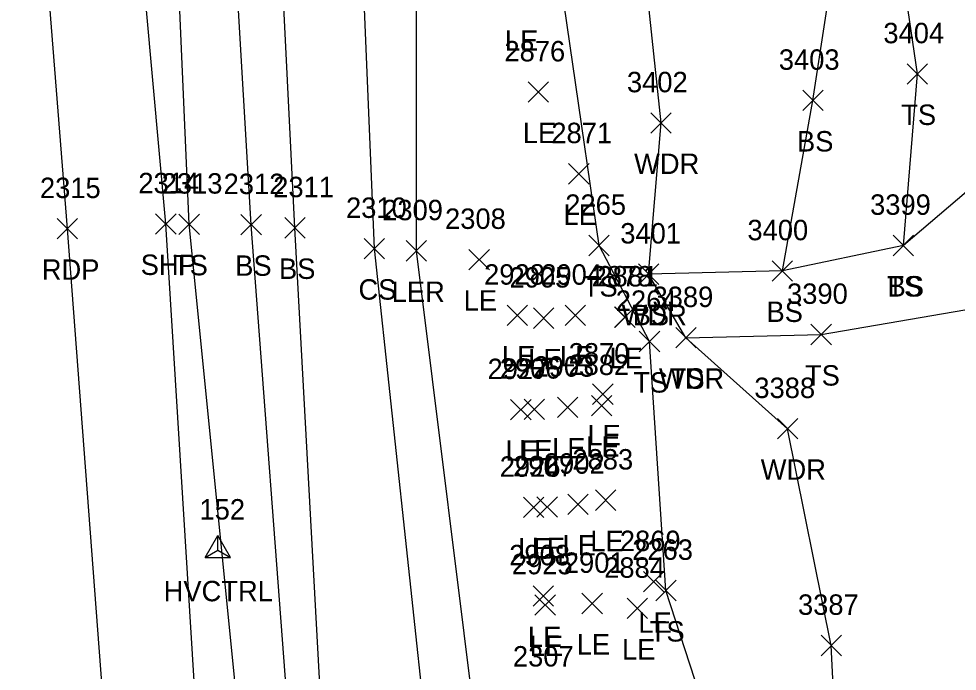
# Model space of a CAD drawing. Extents: x 1650221 to 1650634, y 244606 to 249996.
# Drawn here: x 1650346.1 to 1650438, y 246557.6 to 246621.5 of the extents above; entities that cross this region are included whole.
import ezdxf

# ---------------------------------------------------------------- set-up
doc = ezdxf.new("R2010")
doc.units = 0
for name, color, linetype in [('C_A', 7, 'Continuous'), ('C_I', 7, 'Continuous'), ('CPSM', 7, 'Continuous'), ('L_A', 7, 'Continuous'), ('L_I', 7, 'Continuous'), ('L_TIC', 7, 'Continuous'), ('LARO', 7, 'Continuous'), ('LAWA', 7, 'Continuous'), ('LELB', 7, 'Continuous'), ('P_A', 7, 'Continuous'), ('P_I', 7, 'Continuous'), ('P_TIC', 7, 'Continuous'), ('PET', 7, 'Continuous'), ('PSP', 7, 'Continuous')]:
    doc.layers.add(name, color=color, linetype=linetype)

msp = doc.modelspace()

# ---------------------------------------------------------------- linework, layer by layer
at = {"layer": 'CPSM'}
for p, q in [((1650364.338, 246568.725), (1650365.588, 246570.89)), ((1650366.838, 246568.725), (1650365.588, 246570.89)), ((1650365.588, 246569.447), (1650365.588, 246570.89)), ((1650364.338, 246568.725), (1650365.588, 246569.447)), ((1650365.588, 246569.447), (1650365.588, 246569.447)), ((1650365.588, 246569.447), (1650366.838, 246568.725)), ((1650364.338, 246568.725), (1650366.838, 246568.725))]:
    msp.add_line(p, q, dxfattribs=at)
at = {"layer": 'L_TIC'}
for points in [[(1650433.105, 246615.068), (1650435.105, 246617.068)], [(1650435.105, 246615.068), (1650433.105, 246617.068)], [(1650395.972, 246613.294), (1650397.972, 246615.294)], [(1650397.972, 246613.294), (1650395.972, 246615.294)], [(1650422.867, 246612.471), (1650424.867, 246614.471)], [(1650424.867, 246612.471), (1650422.867, 246614.471)], [(1650407.993, 246610.27), (1650409.993, 246612.27)], [(1650409.993, 246610.27), (1650407.993, 246612.27)], [(1650399.945, 246605.288), (1650401.945, 246607.288)], [(1650401.945, 246605.288), (1650399.945, 246607.288)], [(1650361.786, 246600.351), (1650363.786, 246602.351)], [(1650363.786, 246600.351), (1650361.786, 246602.351)], [(1650367.85, 246600.305), (1650369.85, 246602.305)], [(1650369.85, 246600.305), (1650367.85, 246602.305)], [(1650372.138, 246600), (1650374.138, 246602)], [(1650374.138, 246600), (1650372.138, 246602)], [(1650401.921, 246598.271), (1650403.921, 246600.271)], [(1650403.921, 246598.271), (1650401.921, 246600.271)], [(1650431.734, 246598.274), (1650433.734, 246600.274)], [(1650433.734, 246598.274), (1650431.734, 246600.274)], [(1650431.734, 246598.274), (1650433.734, 246600.274)], [(1650433.734, 246598.274), (1650431.734, 246600.274)], [(1650379.924, 246597.971), (1650381.924, 246599.971)], [(1650381.924, 246597.971), (1650379.924, 246599.971)], [(1650384.03, 246597.745), (1650386.03, 246599.745)], [(1650386.03, 246597.745), (1650384.03, 246599.745)], [(1650390.18, 246596.895), (1650392.18, 246598.895)], [(1650392.18, 246596.895), (1650390.18, 246598.895)], [(1650406.773, 246595.466), (1650408.773, 246597.466)], [(1650408.773, 246595.466), (1650406.773, 246597.466)], [(1650406.773, 246595.466), (1650408.773, 246597.466)], [(1650408.773, 246595.466), (1650406.773, 246597.466)], [(1650419.879, 246595.785), (1650421.879, 246597.785)], [(1650421.879, 246595.785), (1650419.879, 246597.785)], [(1650419.879, 246595.785), (1650421.879, 246597.785)], [(1650421.879, 246595.785), (1650419.879, 246597.785)], [(1650393.923, 246591.438), (1650395.923, 246593.438)], [(1650395.923, 246591.438), (1650393.923, 246593.438)], [(1650396.492, 246591.155), (1650398.492, 246593.155)], [(1650398.492, 246591.155), (1650396.492, 246593.155)], [(1650399.598, 246591.434), (1650401.598, 246593.434)], [(1650401.598, 246591.434), (1650399.598, 246593.434)], [(1650404.451, 246591.26), (1650406.451, 246593.26)], [(1650406.451, 246591.26), (1650404.451, 246593.26)], [(1650404.456, 246591.259), (1650406.456, 246593.259)], [(1650406.456, 246591.259), (1650404.456, 246593.259)], [(1650410.429, 246589.247), (1650412.429, 246591.247)], [(1650412.429, 246589.247), (1650410.429, 246591.247)], [(1650410.429, 246589.247), (1650412.429, 246591.247)], [(1650412.429, 246589.247), (1650410.429, 246591.247)], [(1650423.679, 246589.557), (1650425.679, 246591.557)], [(1650425.679, 246589.557), (1650423.679, 246591.557)], [(1650406.868, 246588.874), (1650408.868, 246590.874)], [(1650408.868, 246588.874), (1650406.868, 246590.874)], [(1650402.293, 246583.717), (1650404.293, 246585.717)], [(1650404.293, 246583.717), (1650402.293, 246585.717)], [(1650402.182, 246582.594), (1650404.182, 246584.594)], [(1650404.182, 246582.594), (1650402.182, 246584.594)], [(1650394.263, 246582.194), (1650396.263, 246584.194)], [(1650396.263, 246582.194), (1650394.263, 246584.194)], [(1650395.594, 246582.241), (1650397.594, 246584.241)], [(1650397.594, 246582.241), (1650395.594, 246584.241)], [(1650398.841, 246582.43), (1650400.841, 246584.43)], [(1650400.841, 246582.43), (1650398.841, 246584.43)], [(1650420.393, 246580.34), (1650422.393, 246582.34)], [(1650422.393, 246580.34), (1650420.393, 246582.34)], [(1650395.513, 246572.633), (1650397.513, 246574.633)], [(1650397.513, 246572.633), (1650395.513, 246574.633)], [(1650396.841, 246572.665), (1650398.841, 246574.665)], [(1650398.841, 246572.665), (1650396.841, 246574.665)], [(1650399.861, 246572.934), (1650401.861, 246574.934)], [(1650401.861, 246572.934), (1650399.861, 246574.934)], [(1650402.575, 246573.342), (1650404.575, 246575.342)], [(1650404.575, 246573.342), (1650402.575, 246575.342)], [(1650407.276, 246565.358), (1650409.276, 246567.358)], [(1650409.276, 246565.358), (1650407.276, 246567.358)], [(1650408.477, 246564.503), (1650410.477, 246566.503)], [(1650410.477, 246564.503), (1650408.477, 246566.503)], [(1650396.464, 246563.967), (1650398.464, 246565.967)], [(1650398.464, 246563.967), (1650396.464, 246565.967)], [(1650396.643, 246563.088), (1650398.643, 246565.088)], [(1650398.643, 246563.088), (1650396.643, 246565.088)], [(1650401.248, 246563.228), (1650403.248, 246565.228)], [(1650403.248, 246563.228), (1650401.248, 246565.228)], [(1650405.684, 246562.747), (1650407.684, 246564.747)], [(1650407.684, 246562.747), (1650405.684, 246564.747)], [(1650424.665, 246559.118), (1650426.665, 246561.118)], [(1650426.665, 246559.118), (1650424.665, 246561.118)]]:
    msp.add_lwpolyline(points, dxfattribs=at)
at = {"layer": 'LARO'}
msp.add_lwpolyline([(1650408.62, 246217.57), (1650415.017, 246258.551), (1650416.029, 246285.891), (1650409.424, 246296.822), (1650403.385, 246341.569), (1650407.268, 246374.549), (1650399.81, 246378.857), (1650397.578, 246413.378), (1650396.61, 246418.121), (1650404.549, 246441.775), (1650400.932, 246459.086), (1650402.014, 246482.667), (1650393.668, 246489.39), (1650391.868, 246506.076), (1650398.297, 246543.788), (1650391.282, 246548.764), (1650385.03, 246598.745), (1650385.051, 246648.918)], dxfattribs=at)
at = {"layer": 'LAWA'}
msp.add_lwpolyline([(1650467.45, 246241.248), (1650457.439, 246253.738), (1650465.182, 246273.586), (1650462.121, 246310.217), (1650448.311, 246306.896), (1650448.47, 246334.537), (1650451.184, 246360.806), (1650449.397, 246391.825), (1650443.671, 246414.288), (1650436.755, 246442.34), (1650433.959, 246470.022), (1650430.335, 246504.777), (1650427.125, 246530.837), (1650425.665, 246560.118), (1650421.393, 246581.34), (1650411.429, 246590.247), (1650407.773, 246596.466), (1650408.993, 246611.27), (1650406.472, 246635.271)], dxfattribs=at)
at = {"layer": 'LELB'}
for points in [[(1650393.271, 246215.062), (1650388.589, 246258.034), (1650385.303, 246297.22), (1650382.892, 246338.269), (1650379.783, 246382.543), (1650376.697, 246415.11), (1650373.391, 246460.521), (1650370.351, 246509.107), (1650367.729, 246551.788), (1650362.786, 246601.351), (1650360.906, 246643.926), (1650360.73, 246683.447), (1650355.99, 246728.594), (1650353.015, 246770.02), (1650352.21, 246793.578), (1650347.695, 246827.184)], [(1650406.656, 246218.25), (1650409.738, 246258.013), (1650404.964, 246296.74), (1650400.855, 246340.502), (1650395.586, 246379.715), (1650393.167, 246415.096), (1650394.545, 246457.778), (1650389.364, 246506.838), (1650386.116, 246550.614), (1650380.924, 246598.971), (1650378.983, 246645.95), (1650376.234, 246684.957), (1650377.195, 246729.688), (1650373.963, 246768.954), (1650374.901, 246794.969)], [(1650398.424, 246215.354), (1650393.502, 246258.252), (1650390.33, 246297.072), (1650387.572, 246339.17), (1650383.093, 246382.589), (1650381.544, 246415.749), (1650379.325, 246460.798), (1650374.717, 246508.954), (1650372.604, 246551.632), (1650368.85, 246601.305), (1650366.306, 246644.434), (1650364.471, 246684.577), (1650363.627, 246728.256), (1650358.66, 246769.405), (1650355.434, 246788.128), (1650360.397, 246788.442)], [(1650402.25, 246216.694), (1650398.468, 246258.758), (1650395.79, 246297.148), (1650391.97, 246340.099), (1650387.542, 246382.066), (1650385.712, 246415.977), (1650383.049, 246460.21), (1650379.089, 246508.869), (1650375.792, 246552.139), (1650373.138, 246601), (1650370.951, 246644.961), (1650368.354, 246684.963), (1650367.995, 246727.841), (1650362.742, 246769.205), (1650360.397, 246788.442)], [(1650479.188, 246312.479), (1650486.776, 246343.044), (1650484.859, 246368.885), (1650480.94, 246392.324), (1650477.18, 246421.111), (1650468.88, 246443.019), (1650461.433, 246474.295), (1650459.987, 246504.257), (1650455.481, 246533.7), (1650468.385, 246557.946), (1650462.638, 246596.825), (1650458.651, 246616.056), (1650445.954, 246610.519), (1650432.734, 246599.274), (1650420.879, 246596.785), (1650423.867, 246613.471), (1650428.269, 246642.152), (1650440.667, 246654.815), (1650470.876, 246672.082), (1650450.604, 246689.528), (1650437.538, 246708.061), (1650451.689, 246713.269), (1650467.717, 246712.4)], [(1650432.734, 246599.274), (1650434.105, 246616.068), (1650430.603, 246639.796), (1650437.178, 246643.481), (1650472.861, 246649.811)], [(1650445.175, 246217.398), (1650445.531, 246269.295), (1650441.896, 246297.748), (1650443.518, 246304.658), (1650437.793, 246334.622), (1650435.282, 246374.906), (1650430.354, 246416.998), (1650432.132, 246431.963), (1650424.254, 246446.431), (1650422.05, 246472.523), (1650416.532, 246502.712), (1650417.529, 246540.777), (1650409.477, 246565.503), (1650407.868, 246589.874), (1650402.921, 246599.271), (1650397.783, 246634.795)], [(1650420.879, 246596.785), (1650407.773, 246596.466)], [(1650411.429, 246590.247), (1650424.679, 246590.557), (1650443.131, 246593.728), (1650456.989, 246596.575)]]:
    msp.add_lwpolyline(points, dxfattribs=at)
at = {"layer": 'P_TIC'}
for points in [[(1650359.5, 246600.385), (1650361.5, 246602.385)], [(1650361.5, 246600.385), (1650359.5, 246602.385)], [(1650349.862, 246599.915), (1650351.862, 246601.915)], [(1650351.862, 246599.915), (1650349.862, 246601.915)]]:
    msp.add_lwpolyline(points, dxfattribs=at)
at = {"layer": 'PET'}
msp.add_lwpolyline([(1650378.627, 246214.911), (1650375.804, 246256.561), (1650373.007, 246296.437), (1650370.077, 246336.196), (1650366.982, 246382.901), (1650364.952, 246414.805), (1650361.941, 246459.783), (1650357.931, 246508.739), (1650354.58, 246551.739), (1650350.862, 246600.915), (1650347.478, 246643.699), (1650346.095, 246667.406)], dxfattribs=at)
at = {"layer": 'PSP'}
msp.add_lwpolyline([(1650388.25, 246215.072), (1650385.023, 246257.594), (1650382.118, 246297.012), (1650379.042, 246337.668), (1650376.285, 246382.909), (1650373.452, 246415.126), (1650370.449, 246460.184), (1650366.828, 246508.934), (1650363.56, 246551.911), (1650360.5, 246601.385), (1650356.679, 246643.626), (1650355.129, 246668.21)], dxfattribs=at)

# ---------------------------------------------------------------- texts
at = {"layer": 'C_A'}
msp.add_text('HVCTRL', height=2, dxfattribs=at).set_placement((1650360.281, 246564.447))
at = {"layer": 'C_I'}
msp.add_text('152', height=2, dxfattribs=at).set_placement((1650363.793, 246572.447))
at = {"layer": 'L_A'}
for s, p in [('LE', (1650393.702, 246618.335)), ('TS', (1650432.515, 246611.068)), ('LE', (1650395.46, 246609.294)), ('BS', (1650422.308, 246608.471)), ('WDR', (1650406.355, 246606.27)), ('LE', (1650399.433, 246601.288)), ('TS', (1650361.195, 246596.351)), ('BS', (1650367.291, 246596.305)), ('BS', (1650371.579, 246596)), ('CS', (1650379.365, 246593.971)), ('LER', (1650382.613, 246593.745)), ('TS', (1650401.33, 246594.271)), ('TS', (1650431.144, 246594.274)), ('BS', (1650431.175, 246594.274)), ('LE', (1650389.668, 246592.895)), ('BS', (1650419.32, 246591.785)), ('BS', (1650419.32, 246591.785)), ('WDR', (1650405.135, 246591.466)), ('BS', (1650406.214, 246591.466)), ('LE', (1650393.411, 246587.438)), ('LE', (1650399.086, 246587.434)), ('LE', (1650403.939, 246587.26)), ('LE', (1650403.944, 246587.259)), ('LE', (1650395.98, 246587.155)), ('TS', (1650423.089, 246585.557)), ('TS', (1650406.277, 246584.874)), ('WDR', (1650408.791, 246585.247)), ('TS', (1650409.838, 246585.247)), ('LE', (1650401.781, 246579.717)), ('LE', (1650393.751, 246578.194)), ('LE', (1650395.082, 246578.241)), ('LE', (1650398.329, 246578.43)), ('LE', (1650401.67, 246578.594)), ('WDR', (1650418.755, 246576.34)), ('LE', (1650399.349, 246568.934)), ('LE', (1650402.063, 246569.342)), ('LE', (1650395.002, 246568.633)), ('LE', (1650396.329, 246568.665)), ('LE', (1650406.765, 246561.358)), ('TS', (1650407.887, 246560.503)), ('LE', (1650395.952, 246559.967)), ('LE', (1650396.131, 246559.088)), ('LE', (1650400.736, 246559.228)), ('LE', (1650405.172, 246558.747))]:
    msp.add_text(s, height=2, dxfattribs=at).set_placement(p)
at = {"layer": 'L_I'}
for s, p in [('3404', (1650430.767, 246619.068)), ('2876', (1650393.657, 246617.294)), ('3403', (1650420.528, 246616.471)), ('3402', (1650405.655, 246614.27)), ('2871', (1650398.252, 246609.288)), ('2313', (1650360.093, 246604.351)), ('2312', (1650366.157, 246604.305)), ('2311', (1650371.012, 246604)), ('2310', (1650378.144, 246601.971)), ('2265', (1650399.614, 246602.271)), ('3399', (1650429.466, 246602.274)), ('3399', (1650429.466, 246602.274)), ('2309', (1650381.684, 246601.745)), ('2308', (1650387.841, 246600.895)), ('3401', (1650405.002, 246599.466)), ('3401', (1650405.002, 246599.466)), ('3400', (1650417.454, 246599.785)), ('3400', (1650417.454, 246599.785)), ('2928', (1650391.663, 246595.438)), ('2904', (1650397.26, 246595.434)), ('2905', (1650394.153, 246595.155)), ('2878', (1650402.196, 246595.259)), ('2881', (1650402.758, 246595.26)), ('2264', (1650404.561, 246592.874)), ('3389', (1650408.161, 246593.247)), ('3389', (1650408.161, 246593.247)), ('3390', (1650421.333, 246593.557)), ('2870', (1650399.947, 246587.717)), ('2906', (1650393.2, 246586.241)), ('2903', (1650396.502, 246586.43)), ('2882', (1650399.922, 246586.594)), ('2927', (1650392.003, 246586.194)), ('3388', (1650418.133, 246584.34)), ('2883', (1650400.315, 246577.342)), ('2926', (1650393.198, 246576.633)), ('2907', (1650394.503, 246576.665)), ('2902', (1650397.522, 246576.934)), ('2869', (1650404.961, 246569.358)), ('2908', (1650394.126, 246567.967)), ('2263', (1650406.17, 246568.503)), ('2925', (1650394.383, 246567.088)), ('2901', (1650399.476, 246567.228)), ('2884', (1650403.424, 246566.747)), ('3387', (1650422.405, 246563.118)), ('2307', (1650394.487, 246558.059))]:
    msp.add_text(s, height=2, dxfattribs=at).set_placement(p)
at = {"layer": 'P_A'}
for s, p in [('SHP', (1650358.035, 246596.385)), ('RDP', (1650348.35, 246595.915))]:
    msp.add_text(s, height=2, dxfattribs=at).set_placement(p)
at = {"layer": 'P_I'}
for s, p in [('2315', (1650348.169, 246603.915)), ('2314', (1650357.807, 246604.385))]:
    msp.add_text(s, height=2, dxfattribs=at).set_placement(p)

doc.saveas('drawing.dxf')
